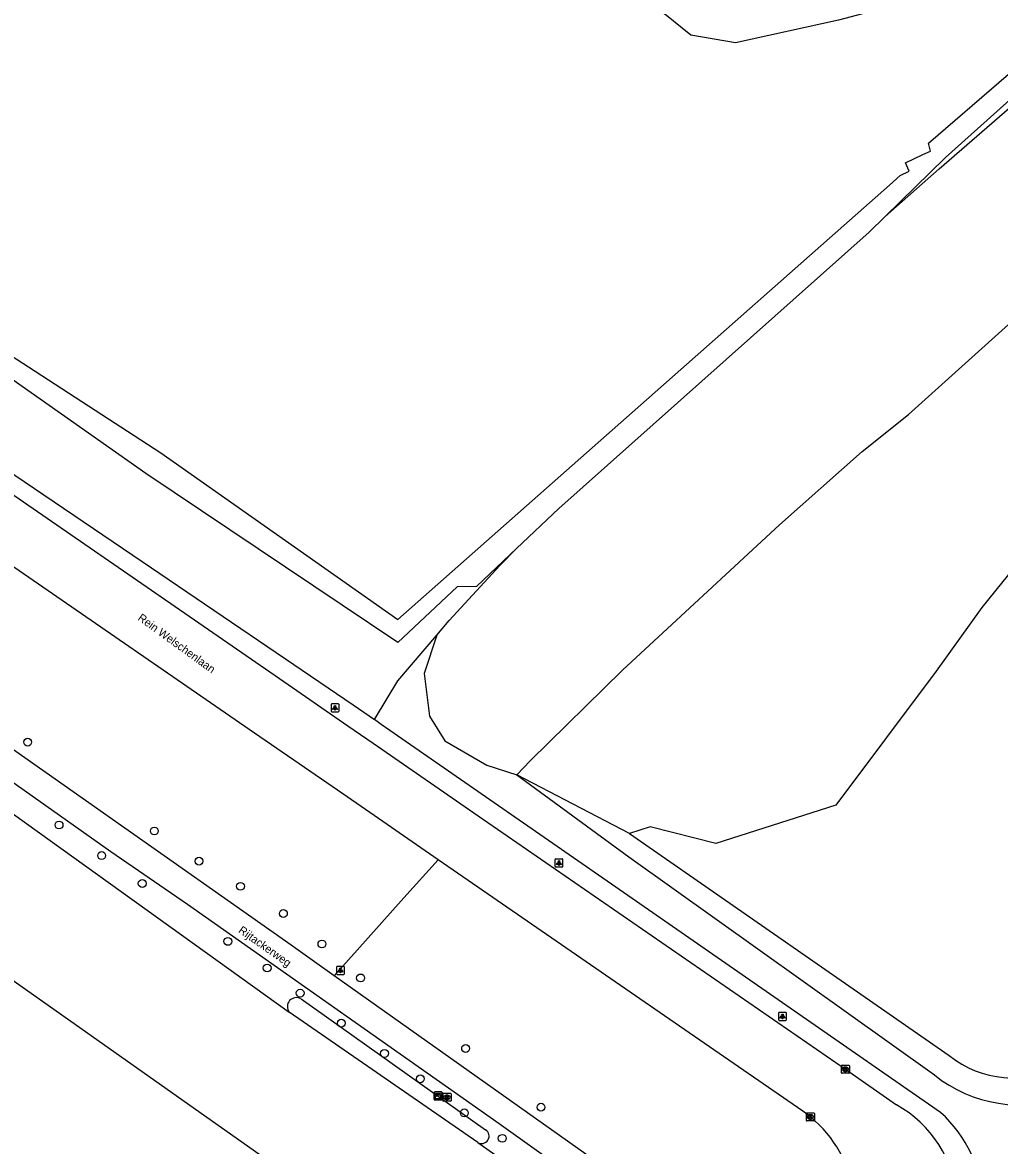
# Model space of a CAD drawing. Extents: x 155209 to 156823, y 385356 to 388482.
# Drawn here: x 156114.9 to 156237, y 386069.7 to 386210 of the extents above; entities that cross this region are included whole.
import ezdxf

# ---------------------------------------------------------------- set-up
doc = ezdxf.new("R2010")
doc.units = 0
for name, color, linetype in [('IMGEO_Berm_groen', 7, 'Continuous'), ('IMGEO_Boom', 7, 'Continuous'), ('IMGEO_Grasland_overig', 7, 'Continuous'), ('IMGEO_Groenvoorziening', 7, 'Continuous'), ('IMGEO_Kast', 7, 'Continuous'), ('IMGEO_Kolk', 7, 'Continuous'), ('IMGEO_Lichtpunt', 7, 'Continuous'), ('IMGEO_Loofbos', 7, 'Continuous'), ('IMGEO_Meer_plas_ven_vijver', 7, 'Continuous'), ('IMGEO_Openbare_ruimte_label', 7, 'Continuous'), ('IMGEO_Parkeervlak_gesloten', 7, 'Continuous'), ('IMGEO_Rijbaan_lokaal_gesloten', 7, 'Continuous'), ('IMGEO_Rioolput', 7, 'Continuous'), ('IMGEO_Waterloop', 7, 'Continuous')]:
    doc.layers.add(name, color=color, linetype=linetype)

msp = doc.modelspace()

# ---------------------------------------------------------------- linework, layer by layer
at = {"layer": 'IMGEO_Berm_groen'}
for points in [[(156097.33, 386122.88), (156148.23, 386086.38)], [(156171.78, 386070.1), (156176.6, 386066.75)]]:
    msp.add_lwpolyline(points, dxfattribs=at)
at = {"layer": 'IMGEO_Boom'}
for centre in [(156115.55, 386120.11), (156119.48, 386109.76), (156131.38, 386109.01), (156124.8, 386105.94), (156136.97, 386105.24), (156129.87, 386102.45), (156142.14, 386102.1), (156147.51, 386098.7), (156140.57, 386095.22), (156152.32, 386094.9), (156145.48, 386091.9), (156157.15, 386090.66), (156149.6, 386088.76), (156154.74, 386085.01), (156170.27, 386081.85), (156160.14, 386081.23), (156164.62, 386078.06), (156170.11, 386073.8), (156179.69, 386074.51), (156174.85, 386070.63)]:
    msp.add_circle(centre, 0.489, dxfattribs=at)
at = {"layer": 'IMGEO_Grasland_overig'}
for points in [[(156194.39, 386323.19), (156196.87, 386319.48), (156193.29, 386316.59), (156209.47, 386289.43), (156227.44, 386257.05), (156246.08, 386222.25), (156249.56, 386214.98), (156250.28, 386211.79), (156248.68, 386209.64), (156230.23, 386193.11), (156222.7, 386185.75)], [(156158.89, 386122.92), (156160.48, 386125.54), (156161.8, 386127.78), (156166.67, 386133.47)], [(156229.62, 386073.86), (156191.09, 386100.59), (156159.73, 386122.33), (156159.41, 386122.56), (156158.89, 386122.92)], [(156176.68, 386116.02), (156190.67, 386105.78), (156228.84, 386078.54)], [(156190.74, 386108.68), (156176.68, 386116.02)]]:
    msp.add_lwpolyline(points, dxfattribs=at)
for centre, radius, start, end in [((156239.58, 386091.98), 17.2, 231.3793, 290.38), ((156218.47, 386061.62), 16.56, 319.8671, 47.6837)]:
    msp.add_arc(centre, radius, start, end, dxfattribs=at)
at = {"layer": 'IMGEO_Groenvoorziening'}
for points in [[(156176.65, 386144.29), (156171.62, 386139.54), (156169.23, 386139.5), (156161.8, 386132.54), (156130.32, 386153.68), (156108.77, 386168.78), (156097.92, 386175.59)], [(156084.49, 386173.39), (156095.53, 386165.91), (156129.85, 386142.65), (156147.77, 386130.5), (156156.24, 386124.76), (156158.89, 386122.92)]]:
    msp.add_lwpolyline(points, dxfattribs=at)
at = {"layer": 'IMGEO_Kast'}
for p, q in [((156166.33, 386075.51), (156166.33, 386076.35)), ((156166.33, 386076.35), (156166.33, 386075.51)), ((156166.41, 386076.43), (156167.25, 386076.43)), ((156167.25, 386076.43), (156166.41, 386076.43)), ((156167.26, 386075.43), (156166.42, 386075.43)), ((156166.42, 386075.43), (156167.26, 386075.43)), ((156167.33, 386076.36), (156167.33, 386075.52)), ((156167.33, 386075.52), (156167.33, 386076.36))]:
    msp.add_line(p, q, dxfattribs=at)
for points in [[(156166.53, 386076.22), (156167.13, 386076.22), (156167.13, 386076.14), (156166.53, 386076.14), (156166.53, 386076.22)], [(156166.53, 386076.05), (156167.13, 386076.05), (156167.13, 386075.56), (156166.53, 386075.56), (156166.53, 386076.05)]]:
    msp.add_lwpolyline(points, dxfattribs=at)
msp.add_circle((156166.61, 386075.9), 0.0377, dxfattribs=at)
for centre, start, end in [((156166.41, 386076.35), 92.4484, 184.2845), ((156166.41, 386076.35), 92.4484, 184.2845), ((156166.41, 386075.51), 182.4484, 274.2845), ((156166.41, 386075.51), 182.4484, 274.2845), ((156167.25, 386076.35), 2.4484, 94.2845), ((156167.25, 386076.35), 2.4484, 94.2845), ((156167.25, 386075.51), 272.4484, 4.2845), ((156167.25, 386075.51), 272.4484, 4.2845)]:
    msp.add_arc(centre, 0.0779, start, end, dxfattribs=at)
at = {"layer": 'IMGEO_Kolk'}
for p, q in [((156217.23, 386078.82), (156217.23, 386079.68)), ((156217.3, 386079.75), (156218.16, 386079.75)), ((156217.72, 386079.53), (156217.74, 386079.53)), ((156218.23, 386079.68), (156218.23, 386078.82)), ((156218.16, 386078.75), (156217.3, 386078.75)), ((156217.74, 386078.97), (156217.71, 386078.97)), ((156212.85, 386072.87), (156212.85, 386073.73)), ((156212.92, 386073.8), (156213.77, 386073.8)), ((156213.77, 386072.8), (156212.92, 386072.8)), ((156213.33, 386073.58), (156213.36, 386073.58)), ((156213.36, 386073.02), (156213.33, 386073.02)), ((156213.85, 386073.73), (156213.85, 386072.87))]:
    msp.add_line(p, q, dxfattribs=at)
for points in [[(156217.23, 386078.82), (156217.23, 386079.68)], [(156217.3, 386079.75), (156218.16, 386079.75)], [(156218.23, 386079.68), (156218.23, 386078.82)], [(156218.16, 386078.75), (156217.3, 386078.75)], [(156217.55, 386079.45), (156217.67, 386079.45), (156217.67, 386079.3), (156217.8, 386079.45), (156217.97, 386079.45), (156217.82, 386079.3), (156217.97, 386079.05), (156217.82, 386079.05), (156217.74, 386079.21), (156217.67, 386079.15), (156217.67, 386079.05), (156217.55, 386079.05), (156217.55, 386079.45)], [(156212.85, 386072.87), (156212.85, 386073.73)], [(156212.92, 386073.8), (156213.77, 386073.8)], [(156213.77, 386072.8), (156212.92, 386072.8)], [(156213.17, 386073.5), (156213.29, 386073.5), (156213.29, 386073.35), (156213.42, 386073.5), (156213.58, 386073.5), (156213.44, 386073.35), (156213.59, 386073.1), (156213.44, 386073.1), (156213.35, 386073.26), (156213.29, 386073.2), (156213.29, 386073.1), (156213.17, 386073.1), (156213.17, 386073.5)], [(156213.85, 386073.73), (156213.85, 386072.87)]]:
    msp.add_lwpolyline(points, dxfattribs=at)
for centre, start, end in [((156217.31, 386079.67), 91.552, 178.448), ((156217.31, 386079.67), 91.552, 178.448), ((156218.15, 386079.67), 1.552, 88.448), ((156218.15, 386079.67), 1.552, 88.448), ((156217.31, 386078.82), 181.552, 268.448), ((156217.31, 386078.82), 181.552, 268.448), ((156218.15, 386078.82), 271.552, 358.448), ((156218.15, 386078.82), 271.552, 358.448), ((156212.92, 386073.72), 91.552, 178.448), ((156212.92, 386073.72), 91.552, 178.448), ((156212.92, 386072.88), 181.552, 268.448), ((156212.92, 386072.88), 181.552, 268.448), ((156213.77, 386073.72), 1.552, 88.448), ((156213.77, 386073.72), 1.552, 88.448), ((156213.77, 386072.88), 271.552, 358.448), ((156213.77, 386072.88), 271.552, 358.448)]:
    msp.add_arc(centre, 0.0765, start, end, dxfattribs=at)
for centre, major_axis, ratio, start_param, end_param in [((156217.72, 386079.25), (-0.387, 0.002), 0.722429, 4.712389, 7.853982), ((156217.74, 386079.25), (-0.39, 0.002), 0.717154, 1.570796, 4.712389), ((156213.33, 386073.3), (-0.387, 0.002), 0.722429, 4.712389, 7.853982), ((156213.36, 386073.3), (-0.39, 0.002), 0.717154, 1.570796, 4.712389)]:
    msp.add_ellipse(centre, major_axis=major_axis, ratio=ratio, start_param=start_param, end_param=end_param, dxfattribs=at)
at = {"layer": 'IMGEO_Lichtpunt'}
for p, q in [((156153.46, 386124.8), (156153.46, 386124)), ((156153.46, 386124.8), (156153.46, 386124)), ((156154.36, 386124.9), (156153.56, 386124.9)), ((156154.36, 386124.9), (156153.56, 386124.9)), ((156154.46, 386124), (156154.46, 386124.8)), ((156154.46, 386124), (156154.46, 386124.8)), ((156153.56, 386123.9), (156154.36, 386123.9)), ((156153.56, 386123.9), (156154.36, 386123.9)), ((156181.44, 386105.42), (156181.44, 386104.61)), ((156181.44, 386105.42), (156181.44, 386104.61)), ((156182.34, 386105.51), (156181.53, 386105.51)), ((156182.34, 386105.51), (156181.53, 386105.51)), ((156182.43, 386104.61), (156182.43, 386105.42)), ((156182.43, 386104.61), (156182.43, 386105.42)), ((156181.53, 386104.52), (156182.34, 386104.52)), ((156181.53, 386104.52), (156182.34, 386104.52)), ((156155.04, 386092.09), (156154.23, 386092.09)), ((156155.04, 386092.09), (156154.23, 386092.09)), ((156154.13, 386092), (156154.13, 386091.19)), ((156154.13, 386092), (156154.13, 386091.19)), ((156154.23, 386091.1), (156155.04, 386091.1)), ((156154.23, 386091.1), (156155.04, 386091.1)), ((156155.13, 386091.19), (156155.13, 386092)), ((156155.13, 386091.19), (156155.13, 386092)), ((156209.36, 386086.26), (156209.36, 386085.45)), ((156209.36, 386086.26), (156209.36, 386085.45)), ((156210.26, 386086.35), (156209.46, 386086.35)), ((156210.26, 386086.35), (156209.46, 386086.35)), ((156209.46, 386085.35), (156210.26, 386085.35)), ((156209.46, 386085.35), (156210.26, 386085.35)), ((156210.36, 386085.45), (156210.36, 386086.26)), ((156210.36, 386085.45), (156210.36, 386086.26))]:
    msp.add_line(p, q, dxfattribs=at)
for points in [[(156153.84, 386124.47), (156153.87, 386124.44), (156153.69, 386124.18), (156153.65, 386124.2), (156153.84, 386124.47)], [(156153.94, 386124.42), (156153.98, 386124.42), (156153.98, 386124.1), (156153.94, 386124.1), (156153.94, 386124.42)], [(156154.05, 386124.44), (156154.09, 386124.47), (156154.27, 386124.2), (156154.23, 386124.18), (156154.05, 386124.44)], [(156181.81, 386105.08), (156181.85, 386105.05), (156181.66, 386104.79), (156181.62, 386104.82), (156181.81, 386105.08)], [(156181.91, 386105.03), (156181.96, 386105.03), (156181.96, 386104.71), (156181.91, 386104.71), (156181.91, 386105.03)], [(156182.02, 386105.05), (156182.06, 386105.08), (156182.25, 386104.82), (156182.21, 386104.79), (156182.02, 386105.05)], [(156154.51, 386091.66), (156154.55, 386091.63), (156154.36, 386091.37), (156154.32, 386091.4), (156154.51, 386091.66)], [(156154.61, 386091.61), (156154.66, 386091.61), (156154.66, 386091.29), (156154.61, 386091.29), (156154.61, 386091.61)], [(156154.72, 386091.63), (156154.76, 386091.66), (156154.94, 386091.4), (156154.91, 386091.37), (156154.72, 386091.63)], [(156209.74, 386085.92), (156209.78, 386085.89), (156209.59, 386085.63), (156209.55, 386085.66), (156209.74, 386085.92)], [(156209.84, 386085.87), (156209.89, 386085.87), (156209.89, 386085.55), (156209.84, 386085.55), (156209.84, 386085.87)], [(156209.95, 386085.89), (156209.99, 386085.92), (156210.17, 386085.66), (156210.14, 386085.63), (156209.95, 386085.89)]]:
    msp.add_lwpolyline(points, dxfattribs=at)
for centre in [(156153.96, 386124.6), (156181.94, 386105.22), (156154.63, 386091.8), (156209.86, 386086.05)]:
    msp.add_circle(centre, 0.0994, dxfattribs=at)
for centre, start, end in [((156153.56, 386124.8), 90, 180), ((156153.56, 386124.8), 90, 180), ((156154.36, 386124.8), 0, 90), ((156154.36, 386124.8), 0, 90), ((156153.56, 386124), 180, 270), ((156153.56, 386124), 180, 270), ((156154.36, 386124), 270, 0), ((156154.36, 386124), 270, 360), ((156181.53, 386105.42), 90, 180), ((156181.53, 386105.42), 90, 180), ((156182.34, 386105.42), 0, 90), ((156182.34, 386105.42), 0, 90), ((156181.53, 386104.61), 180, 270), ((156181.53, 386104.61), 180, 270), ((156182.34, 386104.61), 270, 0), ((156182.34, 386104.61), 270, 360), ((156154.23, 386092), 90, 180), ((156154.23, 386092), 90, 180), ((156155.04, 386092), 0, 90), ((156155.04, 386092), 0, 90), ((156154.23, 386091.19), 180, 270), ((156154.23, 386091.19), 180, 270), ((156155.04, 386091.19), 270, 0), ((156155.04, 386091.19), 270, 360), ((156209.46, 386086.26), 90, 180), ((156209.46, 386086.26), 90, 180), ((156209.46, 386085.45), 180, 270), ((156209.46, 386085.45), 180, 270), ((156210.26, 386086.26), 0, 90), ((156210.26, 386086.26), 0, 90), ((156210.26, 386085.45), 270, 0), ((156210.26, 386085.45), 270, 360)]:
    msp.add_arc(centre, 0.0946, start, end, dxfattribs=at)
at = {"layer": 'IMGEO_Loofbos'}
for points in [[(156222.7, 386185.75), (156229.45, 386191.71), (156252.35, 386211.57), (156254.86, 386213.75)], [(156176.68, 386116.02), (156178.33, 386117.77), (156189.89, 386129.1), (156209.51, 386147.24), (156219.81, 386156.41), (156225.61, 386161.04), (156246.86, 386180.12), (156255.17, 386187.18), (156255.25, 386187.24)], [(156222.7, 386185.75), (156220.7, 386183.8), (156181.94, 386149.28), (156176.65, 386144.29)], [(156166.67, 386133.47), (156168.23, 386135.29), (156174.54, 386142.16), (156176.65, 386144.29)], [(156166.67, 386133.47), (156165.11, 386128.7), (156165.75, 386123.37), (156167.66, 386120.27), (156172.91, 386117.25), (156176.68, 386116.02)], [(156153.85, 386090.94), (156156.71, 386094.13), (156162.57, 386100.65), (156166.86, 386105.42)]]:
    msp.add_lwpolyline(points, dxfattribs=at)
at = {"layer": 'IMGEO_Meer_plas_ven_vijver'}
for points in [[(156247.07, 386216.12), (156237.78, 386215.24), (156231.88, 386213.32), (156228.84, 386213.49), (156216.86, 386210.3), (156204, 386207.47), (156198.41, 386208.42), (156195.15, 386211.02), (156191.99, 386216.04), (156190.79, 386220.33), (156192.16, 386232.19), (156191.91, 386249.28), (156186.73, 386259.43), (156182.97, 386266.48), (156185.02, 386274.21), (156191.06, 386287.31), (156194.77, 386298.75), (156197.31, 386305.14)], [(156129.19, 386259.44), (156101.58, 386176.93), (156109.91, 386170.67), (156132.18, 386156.24), (156161.82, 386135.42), (156223.23, 386189.68), (156224.56, 386190.89), (156225.68, 386191.41), (156225.25, 386192.45), (156227.39, 386193.5), (156228.36, 386193.93), (156228.11, 386194.93), (156248.12, 386212.14)], [(156244.82, 386145.79), (156244.23, 386145.52), (156244.7, 386144.49), (156239.69, 386143.01), (156234.77, 386136.94), (156229.06, 386128.99), (156216.55, 386112.22), (156201.55, 386107.46), (156193.35, 386109.51), (156190.74, 386108.68)], [(156190.74, 386108.68), (156230.7, 386080.95)]]:
    msp.add_lwpolyline(points, dxfattribs=at)
msp.add_arc((156238.76, 386091.17), 13.02, 231.7062, 297.3831, dxfattribs=at)
at = {"layer": 'IMGEO_Parkeervlak_gesloten'}
msp.add_lwpolyline([(156099.96, 386100.04), (156160, 386057.7), (156157.51, 386054.17), (156161.54, 386051.34)], dxfattribs=at)
at = {"layer": 'IMGEO_Rijbaan_lokaal_gesloten'}
for points in [[(156093, 386165.23), (156101.94, 386159.1), (156147.01, 386128.05), (156155.56, 386122.15), (156158.71, 386119.97), (156171.85, 386110.91), (156217.73, 386079.25), (156224.12, 386074.8)], [(156166.86, 386105.42), (156156.69, 386112.43), (156153.6, 386114.56), (156143.24, 386121.7), (156086.24, 386160.94), (156083.54, 386162.84)], [(156153.85, 386090.94), (156151.39, 386092.68), (156148.48, 386094.74), (156078.08, 386144.22), (156076.42, 386145.39), (156074.85, 386146.49)], [(156209.24, 386046.84), (156203.46, 386051.76), (156174.48, 386072.45), (156135.52, 386099.82), (156125.95, 386106.41), (156097.82, 386126.26)], [(156213.35, 386073.3), (156212.41, 386074.03), (156166.86, 386105.42)], [(156212.18, 386049.2), (156205.14, 386054.59), (156153.85, 386090.94)]]:
    msp.add_lwpolyline(points, dxfattribs=at)
for centre, radius, start, end in [((156216.76, 386061.72), 15.01, 309.227, 60.6168), ((156203.91, 386061.64), 15, 325.5541, 50.996)]:
    msp.add_arc(centre, radius, start, end, dxfattribs=at)
at = {"layer": 'IMGEO_Rioolput'}
for p, q in [((156167.45, 386075.32), (156167.45, 386076.17)), ((156167.52, 386076.25), (156168.37, 386076.25)), ((156167.93, 386076.03), (156167.96, 386076.03)), ((156167.96, 386075.47), (156167.93, 386075.47)), ((156168.45, 386076.17), (156168.45, 386075.32)), ((156168.37, 386075.25), (156167.52, 386075.25))]:
    msp.add_line(p, q, dxfattribs=at)
for points in [[(156167.45, 386075.32), (156167.45, 386076.17)], [(156167.52, 386076.25), (156168.37, 386076.25)], [(156168.03, 386075.95), (156167.78, 386075.95), (156167.78, 386075.55)], [(156167.78, 386075.55), (156167.91, 386075.55), (156167.91, 386075.71), (156167.92, 386075.71)], [(156167.96, 386075.87), (156167.91, 386075.87), (156167.91, 386075.79)], [(156167.91, 386075.79), (156167.96, 386075.79)], [(156167.96, 386075.68), (156168.04, 386075.55), (156168.17, 386075.55), (156168.11, 386075.67)], [(156168.45, 386076.17), (156168.45, 386075.32)], [(156168.37, 386075.25), (156167.52, 386075.25)]]:
    msp.add_lwpolyline(points, dxfattribs=at)
for centre, radius, start, end in [((156167.52, 386076.17), 0.0765, 91.552, 178.448), ((156167.52, 386076.17), 0.0765, 91.552, 178.448), ((156167.52, 386075.32), 0.0765, 181.552, 268.448), ((156167.52, 386075.32), 0.0765, 181.552, 268.448), ((156167.92, 386075.66), 0.0533, 26.0293, 88.6989), ((156167.97, 386075.77), 0.0964, 77.0061, 93.1865), ((156167.94, 386075.98), 0.19, 274.7715, 282.9687), ((156167.98, 386075.83), 0.0378, 276.6634, 79.6772), ((156168.03, 386075.84), 0.109, 350.3612, 89.416), ((156168.03, 386075.84), 0.112, 277.5842, 350.9817), ((156168.02, 386075.62), 0.108, 29.5134, 73.7905), ((156168.37, 386076.17), 0.0765, 1.552, 88.448), ((156168.37, 386076.17), 0.0765, 1.552, 88.448), ((156168.37, 386075.32), 0.0765, 271.552, 358.448), ((156168.37, 386075.32), 0.0765, 271.552, 358.448)]:
    msp.add_arc(centre, radius, start, end, dxfattribs=at)
for centre, major_axis, ratio, start_param, end_param in [((156167.93, 386075.75), (-0.387, 0.002), 0.722429, 4.712389, 7.853982), ((156167.96, 386075.75), (-0.39, 0.002), 0.717154, 1.570796, 4.712389)]:
    msp.add_ellipse(centre, major_axis=major_axis, ratio=ratio, start_param=start_param, end_param=end_param, dxfattribs=at)
at = {"layer": 'IMGEO_Waterloop'}
for points in [[(156149.71, 386088.04), (156172.77, 386071.69)], [(156171.78, 386070.1), (156148.23, 386086.38)]]:
    msp.add_lwpolyline(points, dxfattribs=at)
for centre, radius, start, end in [((156149.13, 386087.07), 1.13, 59.4121, 217.2694), ((156172.27, 386070.9), 0.938, 238.3455, 57.6308)]:
    msp.add_arc(centre, radius, start, end, dxfattribs=at)

# ---------------------------------------------------------------- texts
at = {"layer": 'IMGEO_Openbare_ruimte_label'}
for s, rotation, p in [('Rein Welschenlaan', 323.9895, (156129.23, 386135.43)), ('Rijtackerweg', 324.6888, (156141.8, 386096.41))]:
    msp.add_text(s, height=1, rotation=rotation, dxfattribs=at).set_placement(p)

doc.saveas('drawing.dxf')
